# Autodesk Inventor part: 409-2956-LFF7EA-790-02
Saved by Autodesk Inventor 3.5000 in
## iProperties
Created: 2010-09
Part Number: 409-2956-LFF7EA-790-02
Cost Center: 0 lbmass
Material: A36 STEEL PLATE
Document SubType Name: Sheet Metal
Designer: S. Boerckel
Authority: 0 in^3
Mass: 999.796 g
Surface Area: 319.706 cm^2
Volume: 127.201 cm^3
Density: 7.86 g/cm^3
Flat Pattern Width: 8.89 cm
Flat Pattern Length: 15.24 cm
Flat Pattern Area: 135.484 cm^2
Sheet Metal Rule: 3/8"Thk
Sheet Metal Width: 6.0000 in
Sheet Metal Length: 21.0000 in^2
Description: BASE PLATE
User Status: BURN
SaveDate: 2008-01-15
SaveTime: 10:24
FileName: Sheet Metal
Wide: =<Flat Pattern Width>cm
Length: =<Flat Pattern Length>cm
Thickness: 0.3750 in
SMR: =<Sheet Metal Rule> - <Material>
Author: S. Boerckel
Revision Number: 0
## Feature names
1. Hole1
2. Plate1
